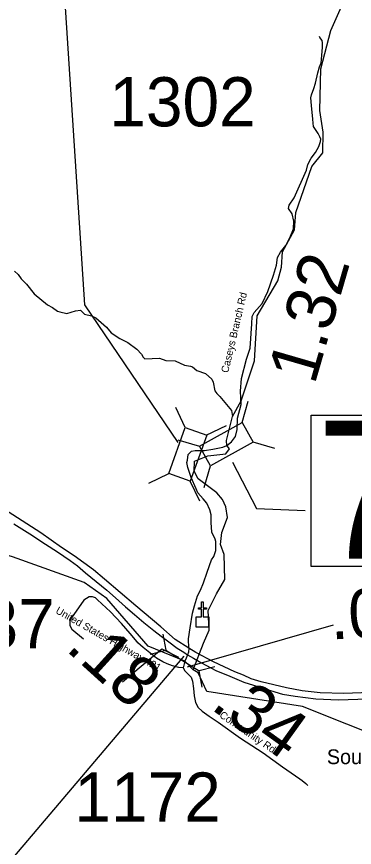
# Model space of a CAD drawing. Extents: x 1248224 to 1454986, y 825081 to 985870.
# Drawn here: x 1290590 to 1294022, y 891703 to 900147 of the extents above; entities that cross this region are included whole.
import ezdxf

# ---------------------------------------------------------------- set-up
doc = ezdxf.new("R2010")
doc.units = 0
for name, color, linetype in [('Exist Cultural Church CELL', 7, 'Continuous'), ('Exist Hydrographic Creek Single Shore', 7, 'Continuous'), ('Exist Hydrographic Misc Water Feature', 7, 'Continuous'), ('Exist Road Non-System Type 51', 7, 'Continuous'), ('Exist Road Primary US Divided Attributed', 7, 'Continuous'), ('Exist Road Secondary Mileage Hundredths English Label', 7, 'Continuous'), ('Exist Road Secondary Structure Culvert CELL', 7, 'Continuous'), ('Exist Road Secondary Structure Culvert Number Label', 7, 'Continuous'), ('Exist Road Secondary Structure Standard Bridge CELL', 7, 'Continuous'), ('Exist Road Secondary Structure Standard Bridge Number Label', 7, 'Continuous'), ('Exist Road Secondary Type 51 Attributed', 7, 'Continuous'), ('Exist Road Secondary Type 51 Label', 7, 'Continuous'), ('Exist Road Secondary Type 51 Number Label', 7, 'Continuous')]:
    doc.layers.add(name, color=color, linetype=linetype)

msp = doc.modelspace()

# ---------------------------------------------------------------- linework, layer by layer
at = {"layer": 'Exist Cultural Church CELL'}
msp.add_lwpolyline([(1292412.8, 894047.3), (1292469.7, 894047.4), (1292469.7, 894123.5), (1292437.7, 894123.5), (1292437.7, 894139.5), (1292469.7, 894139.5), (1292469.7, 894199.7), (1292485.8, 894199.7), (1292485.8, 894139.5), (1292517.8, 894139.5), (1292517.8, 894123.5), (1292485.8, 894123.5), (1292485.8, 894047.4), (1292543.4, 894047.3), (1292543.4, 893940.8), (1292412.8, 893940.8)], close=True, dxfattribs=at)
at = {"layer": 'Exist Hydrographic Creek Single Shore'}
for points in [[(1292298.6, 893596.2), (1291926.7, 893747.9), (1291505.3, 894232.6), (1291277.7, 894395), (1290547.5, 894654.9), (1290205.2, 894753.7), (1289870.8, 894922.8)], [(1292385.6, 893508.8), (1292298.6, 893596.2)], [(1297957.6, 892139.4), (1297705.7, 892062.4), (1297487.9, 891997.1), (1297449.4, 891985.1), (1297412.1, 891974.2), (1297338, 891953.5), (1296534.2, 891835.4), (1296271.7, 891729.9), (1296155.6, 891748.6), (1296024.6, 891863), (1295817.6, 892251.2), (1295688.6, 892437.6), (1295379.6, 892745.8), (1295009.6, 892963.4), (1294792.6, 892974.2), (1294682.7, 892920.6), (1294512.6, 892766.5), (1294395.6, 892775.3), (1293495.1, 893135.7), (1292523.6, 893288.9), (1292434.4, 893477.4), (1292385.6, 893508.8)]]:
    msp.add_lwpolyline(points, dxfattribs=at)
at = {"layer": 'Exist Hydrographic Misc Water Feature'}
for points in [[(1292385.6, 893508.8), (1292489.6, 893777.7), (1292546.6, 893910.1), (1292537.4, 894110), (1292621.9, 894281), (1292704.6, 894426.3), (1292699.1, 894680.9), (1292660.5, 894782), (1292675.2, 894905.2), (1292734, 895057.8), (1292717.4, 895165.5), (1292680.6, 895239), (1292623.5, 895305.9), (1292435.5, 895450.9), (1292395.5, 895527.1), (1292397.5, 895628.8), (1292532.5, 895682), (1292716.5, 895704.5), (1292751.5, 895753.1), (1292725.2, 895788), (1292721.3, 895838.4), (1292784.8, 896084), (1292871.5, 896243.1), (1293006.5, 896647.4), (1293034.4, 897106.6), (1293243.5, 897460.2), (1293280.5, 897600.6), (1293292.5, 897757.9), (1293414.5, 897978.6), (1293427.4, 898155.7), (1293588.5, 898625.2), (1293700.5, 898764.1), (1293705.5, 898974.1), (1293669.5, 899191.5), (1293679.4, 899614.8), (1293781.5, 900006.7), (1293931.4, 900345)], [(1290569.4, 897559.7), (1290604.6, 897526.2), (1290635.6, 897482), (1290690.3, 897428.4), (1290769.9, 897328.3), (1290903.2, 897216.5), (1290954.7, 897191.7), (1291005.8, 897154.5), (1291029.5, 897145.8), (1291101.3, 897129.6), (1291189.9, 897155.8), (1291238.2, 897163), (1291281.1, 897121.9), (1291352.8, 897105.7), (1291394.4, 897084.4), (1291504.1, 896990.3), (1291550.8, 896932.7), (1291637.4, 896874.3), (1291720.5, 896834.9), (1291812.8, 896768.2), (1291859.6, 896714.7), (1291875, 896686.5), (1291894.6, 896670.5), (1292042.7, 896674.1), (1292106.2, 896650.7), (1292202.2, 896648.8), (1292297.2, 896605.8), (1292357.1, 896594.8), (1292376.8, 896586.2), (1292422, 896549.2), (1292509.3, 896518.7), (1292572, 896461.7), (1292587.2, 896432.7), (1292605.1, 896344.5), (1292624.4, 896316.2), (1292655.7, 896287.6), (1292774.2, 896144), (1292784.8, 896084)]]:
    msp.add_lwpolyline(points, dxfattribs=at)
at = {"layer": 'Exist Road Non-System Type 51'}
msp.add_lwpolyline([(1291545.8, 894099.1), (1291413.6, 894218.5), (1291391.8, 894240.3), (1291362.7, 894250), (1291326.4, 894250), (1291273.1, 894216), (1291147.2, 894036.7), (1291130.2, 894005.2), (1291132.6, 893959.2), (1291152, 893922.8), (1291268.3, 893823.4)], dxfattribs=at)
at = {"layer": 'Exist Road Primary US Divided Attributed'}
for points in [[(1292340.5, 893728.9), (1292200.8, 893817.8), (1292054.4, 893944.6), (1291802.7, 894157.8), (1291483, 894429.5), (1291370.9, 894523.7), (1291174.9, 894665.9), (1291046, 894751.6), (1290837.3, 894899.1), (1290597.8, 895053.4), (1290467.7, 895137.1), (1290246.1, 895284.5), (1290014.8, 895435.2), (1289835.2, 895543.5), (1289766.5, 895595), (1289647.8, 895679.8), (1289525.2, 895777.9), (1289416.6, 895878.3), (1289210.3, 896095.6), (1289100.3, 896229), (1289053.5, 896279.8), (1288987.5, 896370.6), (1288913.2, 896468.3)], [(1290563.1, 894991.5), (1290723.8, 894889.5), (1290884, 894785.9), (1291005.8, 894708.8), (1291134.7, 894619.7), (1291208.9, 894566.5), (1291289.7, 894493.4), (1291505.5, 894318.1), (1291594.7, 894241), (1291697.1, 894148.5), (1291789, 894069.7), (1291884.3, 893989.1), (1291983.2, 893908.6), (1292057.4, 893848.6), (1292136.8, 893793.8), (1292222.5, 893728.7), (1292289.6, 893685.9), (1292325.5, 893659.7)], [(1292325.5, 893659.7), (1292386.2, 893625), (1292461.3, 893583.1), (1292621.1, 893499.1), (1292733.2, 893452.8), (1292897.4, 893382.6), (1292995.4, 893350.9), (1293126.1, 893310.6), (1293292.5, 893261.8), (1293420.1, 893240.5), (1293629.1, 893213), (1293858.8, 893204.7), (1294155.1, 893212.1), (1294207.1, 893212.8), (1294378, 893213), (1294515.8, 893216.4), (1294801.8, 893215.5), (1294934.3, 893212.1), (1295117.2, 893204.7), (1295294.6, 893177.2), (1295482.5, 893133.3), (1295528.4, 893124.7), (1295783.4, 893038.2)], [(1295826, 893098.2), (1295773.9, 893111.9), (1295556.7, 893180.4), (1295501.9, 893194.1), (1295418.3, 893219.8), (1295306.9, 893240.5), (1295124, 893270.7), (1294956.2, 893284.5), (1294840.7, 893284.5), (1294570.9, 893285), (1294384.6, 893283.3), (1294204.8, 893275.8), (1294182.9, 893276.4), (1293913.8, 893268), (1293673.1, 893274.9), (1293492.9, 893295.5), (1293333.4, 893325.7), (1293073.5, 893386.3), (1292971.7, 893415.1), (1292893.9, 893452.8), (1292806.1, 893489.1), (1292590.2, 893588.2), (1292412.7, 893684.1), (1292340.5, 893728.9)]]:
    msp.add_lwpolyline(points, dxfattribs=at)
at = {"layer": 'Exist Road Secondary Mileage Hundredths English Label'}
msp.add_line((1292324.8, 893537.9), (1293810.6, 893965.8), dxfattribs=at)
at = {"layer": 'Exist Road Secondary Structure Culvert CELL'}
for p, q in [((1292075.2, 893871), (1292107.9, 893707.7)), ((1291946.6, 893666.1), (1292107.9, 893707.7)), ((1292107.9, 893707.7), (1292443.9, 893496.7)), ((1292605.2, 893538.2), (1292443.9, 893496.7)), ((1292476.6, 893333.4), (1292443.9, 893496.7))]:
    msp.add_line(p, q, dxfattribs=at)
at = {"layer": 'Exist Road Secondary Structure Culvert Number Label'}
msp.add_line((1292289.2, 893645.4), (1290176.1, 891157.3), dxfattribs=at)
at = {"layer": 'Exist Road Secondary Structure Standard Bridge CELL'}
for p, q in [((1292881.2, 896022.1), (1292943.5, 896239.7)), ((1292304.2, 895969.6), (1292207.2, 896174.1)), ((1292517.4, 895893.5), (1292722, 895990.6)), ((1292229.6, 895844.7), (1292447.2, 895782.4)), ((1292991, 895824.2), (1293208.7, 895761.9)), ((1292497.3, 895362.3), (1292559.6, 895579.9)), ((1291932.2, 895405.9), (1292136.7, 895502.9)), ((1292451.9, 895220.7), (1292354.9, 895425.2))]:
    msp.add_line(p, q, dxfattribs=at)
for points in [[(1292447.2, 895782.4), (1292880.7, 896023), (1292993.1, 895820.5), (1292559.6, 895579.9)], [(1292136.7, 895502.9), (1292303.2, 895969.9), (1292521.4, 895892.2), (1292354.9, 895425.2)]]:
    msp.add_lwpolyline(points, close=True, dxfattribs=at)
at = {"layer": 'Exist Road Secondary Structure Standard Bridge Number Label'}
for points in [[(1292231.5, 895818.2), (1291284.5, 897218.2), (1291078.6, 900347.5), (1291243.3, 901871)], [(1292783.4, 895618.2), (1293029, 895149.3), (1293520.3, 895127)]]:
    msp.add_lwpolyline(points, dxfattribs=at)
msp.add_lwpolyline([(1293582.7, 896096.2), (1297298.6, 896096.2), (1297298.6, 894559.7), (1293582.7, 894559.7)], close=True, dxfattribs=at)
at = {"layer": 'Exist Road Secondary Type 51 Attributed'}
for points in [[(1292725.2, 895788), (1292772.2, 895826.7), (1292814.9, 895879.1), (1292830.4, 895950.8), (1292834.3, 896067.2), (1292871.1, 896205), (1292865.3, 896338.8), (1292874.9, 896469.7), (1292927.3, 896665.6), (1292962.2, 896778.1), (1292981.6, 897024.5), (1292983.5, 897099.3), (1293004.8, 897140), (1293086.3, 897231.2), (1293142.5, 897353.4), (1293200.6, 897518.3), (1293229.7, 897620.3), (1293239.4, 897699.8), (1293272.3, 897752.2), (1293324.7, 897822), (1293373.1, 897917.1), (1293404.2, 897990.8), (1293406.1, 898068.4), (1293390.6, 898142.1), (1293353.8, 898196.4), (1293359.5, 898230.8), (1293409.9, 898304.5), (1293535.8, 898585.1), (1293549.4, 898645.3), (1293582.3, 898707.4), (1293626.9, 898767.5), (1293659.8, 898825.5), (1293677.8, 898877.2), (1293680.1, 898901.7), (1293670.5, 898924.6), (1293653.7, 898959.4), (1293606.8, 899030.4), (1293602, 899064), (1293599.6, 899103.7), (1293585.2, 899243.1), (1293580.5, 899322.8), (1293585.3, 899350.4), (1293609.4, 899416.5), (1293626.2, 899470.6), (1293649, 899575.2), (1293667, 899636.5), (1293682.6, 899676.2), (1293687.4, 899712.2), (1293698.1, 899835.2), (1293699.3, 899882.1), (1293693.3, 899903.7), (1293671.7, 899935), (1293668.7, 899944.5)], [(1292333.6, 895695.9), (1292367.8, 895731.8), (1292404.6, 895738.6), (1292500.4, 895738.4), (1292583.8, 895749.1), (1292685.6, 895770.5), (1292725.2, 895788)], [(1292340.5, 893728.9), (1292338.1, 893822.4), (1292355, 893936.2), (1292377.1, 894084), (1292395.8, 894158.7), (1292428.5, 894259.4), (1292459.9, 894317.6), (1292488.3, 894390.9), (1292527, 894500.8), (1292568.8, 894626.3), (1292592.7, 894659.2), (1292615, 894721.5), (1292612.7, 894773.3), (1292613.5, 894811.2), (1292607.6, 894834.8), (1292574.7, 894906.5), (1292567.3, 895005.1), (1292565.8, 895082.3), (1292552.4, 895133.1), (1292524, 895201.9), (1292486.7, 895245.2), (1292429.9, 895306.4), (1292415.1, 895347.7), (1292364.3, 895462.8), (1292328.5, 895562.9), (1292321, 895616.7), (1292325.9, 895637.7), (1292333.6, 895695.9)], [(1292282.7, 893527.9), (1292237.2, 893531.7), (1292175, 893549.8), (1292120.7, 893570.5), (1292076.6, 893588.7), (1292011.9, 893627.5), (1291944.6, 893679.4), (1291892.2, 893720.1), (1291874.7, 893733.8), (1291820.3, 893783), (1291813.7, 893791.2), (1291745.2, 893876.3), (1291657.2, 893979.9), (1291545.8, 894099.1)], [(1292325.5, 893659.7), (1292312.2, 893628.1), (1292298.6, 893596.2), (1292295.7, 893583.9), (1292288.3, 893556.8), (1292282.7, 893527.9)], [(1292340.5, 893728.9), (1292337.5, 893688.6), (1292325.5, 893659.7)], [(1292282.7, 893527.9), (1292297.8, 893496.4), (1292336.3, 893461.9), (1292364.4, 893433.4), (1292377.3, 893392.7), (1292386.6, 893316.7), (1292394, 893244.5), (1292407, 893175.9), (1292434.7, 893125.9), (1292475.4, 893087), (1292547, 893038.2)], [(1292547, 893038.2), (1292638.3, 892975.9), (1292863.5, 892814), (1293094.9, 892665.8), (1293291.1, 892521.3), (1293468.8, 892400.9), (1293491.9, 892383.5), (1293527.2, 892352), (1293549.3, 892332.7)]]:
    msp.add_lwpolyline(points, dxfattribs=at)
at = {"layer": 'Exist Road Secondary Type 51 Label'}
msp.add_lwpolyline([(1291666.6, 893384.8), (1292066.8, 893720.1), (1292234.3, 893636.3)], dxfattribs=at)

# ---------------------------------------------------------------- texts
at = {"layer": 'Exist Hydrographic Creek Single Shore'}
msp.add_text('South', height=150, dxfattribs=at).set_placement((1293742.2, 892549.5))
at = {"layer": 'Exist Road Secondary Mileage Hundredths English Label'}
for s, rotation, p in [('1.32', 73.79946, (1293616.5, 896396)), ('.02', 2.47651, (1293784.2, 893816.7)), ('.18', 317.84435, (1291077.6, 893714.4)), ('.34', 324.28901, (1292548.8, 893118.4))]:
    msp.add_text(s, height=500, rotation=rotation, dxfattribs=at).set_placement(p)
at = {"layer": 'Exist Road Secondary Structure Standard Bridge Number Label'}
msp.add_text('700', height=1400, dxfattribs=at).set_placement((1293632.9, 894638.8))
at = {"layer": 'Exist Road Secondary Type 51 Label'}
for s, rotation, p in [('Caseys Branch Rd', 76.65721, (1292739, 896521.2)), ('United States Highway 421', 330.34428, (1290979.7, 894088.5)), ('Community Rd', 325.59143, (1292644, 893032.2))]:
    msp.add_text(s, height=75, rotation=rotation, dxfattribs=at).set_placement(p)
at = {"layer": 'Exist Road Secondary Type 51 Number Label'}
for s, p in [('1302', (1291532, 899031.6)), ('1237', (1289490.4, 893726.3)), ('1172', (1291177.3, 891964.8))]:
    msp.add_text(s, height=500, dxfattribs=at).set_placement(p)

doc.saveas('drawing.dxf')
